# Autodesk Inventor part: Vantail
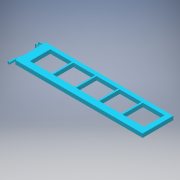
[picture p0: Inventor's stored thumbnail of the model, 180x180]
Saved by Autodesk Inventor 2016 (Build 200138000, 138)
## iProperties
Shininess: 20.0
Length Units: 11269
Angle Units: 11279
Time Units: 11290
Mass Units: 11283
Length Display Precision: 3
Angle Display Precision: 2
Part Number: Vantail
Material: Générique
Document SubType Name: Modeling
Created: 2007-01
Designer: plantier
Mass: 3170.39 g
Surface Area: 3922.97 cm^2
Volume: 3170.39 cm^3
Density: 1 g/cm^3
Appearance: Bleu (ciel - vif)
Density: 0.0
Volumn: 0.0
Area: 0.0
PropertySet Name: Model Information
Control State: 0
Master: False
Checked Out: False
Author: plantier
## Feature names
1. Extrusion1
2. Extrusion2
3. Réseau rectangulaire1 [Rectangular Pattern]
4. Extrusion3
5. Congé1 [Fillet]
6. Réseau rectangulaire2 [Rectangular Pattern]
7. Balayage1
8. Extrusion5
9. Extrusion7
## Parameters: d7 = 0, d9 = 169.49153 mm, d12 = 64.93506 mm, d14 = 0, d17 = 181.81818 mm, d18 = 6 mm, d19 = 35 mm, d22 = 0, d23 = 8 mm, d26 = 25 mm, d31 = 0, d35 = 3.79508 mm, d36 = 0.69575 mm, d38 = 13.68948 mm, d39 = 12.8366 mm, d40 = 19.72522 mm, d41 = 15.63719 mm, d42 = 57.90489 mm, d43 = 9.72522 mm, d44 = 42.01351 mm, d49 = 15 mm, d52 = 0, d53 = 0, d56 = 5 mm, d57 = 0
